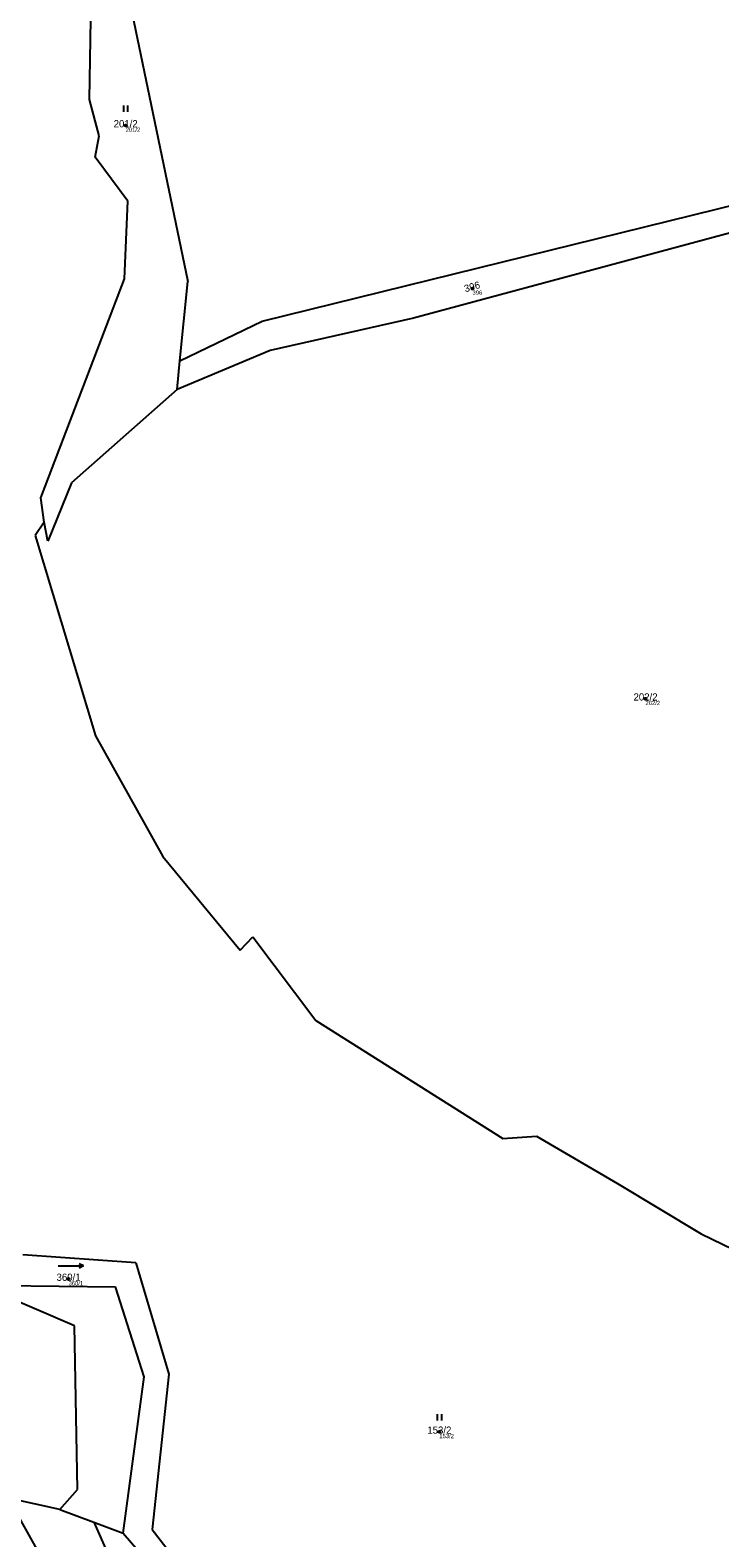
# Model space of a CAD drawing. Extents: x -868010 to -864567, y -1041968 to -1040406.
# Drawn here: x -866804.6 to -866641.3, y -1041599 to -1041242.1 of the extents above; entities that cross this region are included whole.
import ezdxf

# ---------------------------------------------------------------- set-up
doc = ezdxf.new("R2010")
doc.units = 0
for name, color, linetype in [('Definiční body', 7, 'Continuous'), ('Hranice parcel', 7, 'Continuous'), ('Parcelní čísla', 7, 'Continuous'), ('Značky kultur', 7, 'Continuous')]:
    doc.layers.add(name, color=color, linetype=linetype)

msp = doc.modelspace()

# ---------------------------------------------------------------- linework, layer by layer
at = {"layer": 'Definiční body'}
for centre in [(-866781.99, -1041264.71994), (-866699.87, -1041303.28994), (-866658.91, -1041400.40994), (-866795.51, -1041537.76994), (-866707.72, -1041573.95994)]:
    msp.add_circle(centre, 0.25, dxfattribs=at)
at = {"layer": 'Hranice parcel'}
for p, q in [((-866786.48, -1041209.4), (-866767.3, -1041301.64)), ((-866790.52, -1041258.58), (-866790.27, -1041239.55)), ((-866788.22, -1041267.14), (-866790.52, -1041258.58)), ((-866789.24, -1041272.25), (-866788.22, -1041267.14)), ((-866781.45, -1041282.6), (-866789.24, -1041272.25)), ((-866782.23, -1041301.03), (-866781.45, -1041282.6)), ((-866749.65, -1041311.02), (-866636.33, -1041283.07)), ((-866634.71, -1041289.05), (-866713.87, -1041310.31)), ((-866802.06, -1041352.84), (-866782.23, -1041301.03)), ((-866769.16, -1041320.39), (-866767.3, -1041301.64)), ((-866769.16, -1041320.39), (-866749.65, -1041311.02)), ((-866713.87, -1041310.31), (-866747.74, -1041318)), ((-866747.74, -1041318), (-866769.83, -1041327.19)), ((-866769.83, -1041327.19), (-866769.16, -1041320.39)), ((-866769.83, -1041327.19), (-866794.78, -1041349.34)), ((-866794.78, -1041349.34), (-866800.44, -1041363.1)), ((-866801.25, -1041358.65), (-866802.06, -1041352.84)), ((-866801.25, -1041358.65), (-866803.41, -1041361.75)), ((-866800.44, -1041363.1), (-866801.25, -1041358.65)), ((-866803.41, -1041361.75), (-866789.11, -1041409.23)), ((-866789.11, -1041409.23), (-866773.21, -1041437.76)), ((-866773.21, -1041437.76), (-866754.86, -1041459.89)), ((-866754.86, -1041459.89), (-866751.9, -1041456.78)), ((-866751.9, -1041456.78), (-866736.95, -1041476.54)), ((-866736.95, -1041476.54), (-866692.71, -1041504.47)), ((-866692.71, -1041504.47), (-866684.75, -1041503.93)), ((-866684.75, -1041503.93), (-866665.52, -1041515.19)), ((-866665.52, -1041515.19), (-866645.69, -1041527.09)), ((-866645.69, -1041527.09), (-866618.99, -1041540.04)), ((-866794.08, -1041548.87), (-866836.34, -1041530.65)), ((-866779.6, -1041533.91), (-866806.36, -1041532.08)), ((-866779.6, -1041533.91), (-866771.74, -1041560.26)), ((-866811.05, -1041539.28), (-866784.41, -1041539.63)), ((-866777.57, -1041560.94), (-866784.41, -1041539.63)), ((-866793.37, -1041587.63), (-866794.08, -1041548.87)), ((-866782.54, -1041597.89), (-866777.57, -1041560.94)), ((-866771.74, -1041560.26), (-866775.74, -1041597.09)), ((-866797.58, -1041592.36), (-866793.37, -1041587.63)), ((-866797.58, -1041592.36), (-866809.71, -1041589.61)), ((-866797.21, -1041612.03), (-866809.71, -1041589.61)), ((-866797.58, -1041592.36), (-866789.54, -1041595.32)), ((-866789.54, -1041595.32), (-866782.54, -1041597.89)), ((-866789.54, -1041595.32), (-866786.14, -1041602.99)), ((-866782.54, -1041597.89), (-866704.53, -1041688.75)), ((-866775.74, -1041597.09), (-866733.9, -1041650.81))]:
    msp.add_line(p, q, dxfattribs=at)
at = {"layer": 'Značky kultur'}
for p, q in [((-866782.441, -1041261.48), (-866782.441, -1041259.98)), ((-866781.44, -1041261.48), (-866781.44, -1041259.98)), ((-866791.993, -1041534.679), (-866792.97, -1041534.177)), ((-866797.993, -1041534.679), (-866791.993, -1041534.679)), ((-866791.993, -1041534.679), (-866792.97, -1041535.18)), ((-866708.131, -1041571.26), (-866708.131, -1041569.76)), ((-866707.13, -1041571.26), (-866707.13, -1041569.76))]:
    msp.add_line(p, q, dxfattribs=at)

# ---------------------------------------------------------------- texts
at = {"layer": 'Definiční body'}
for s, p in [('201/2', (-866781.99, -1041266.209)), ('396', (-866699.87, -1041304.779)), ('202/2', (-866658.91, -1041401.899)), ('360/1', (-866795.51, -1041539.259)), ('153/2', (-866707.72, -1041575.449))]:
    msp.add_text(s, height=0.999996, dxfattribs=at).set_placement(p)
at = {"layer": 'Parcelní čísla'}
for s, p in [('201/2', (-866784.826, -1041265.145)), ('202/2', (-866661.746, -1041400.835)), ('360/1', (-866798.346, -1041538.195)), ('153/2', (-866710.556, -1041574.385))]:
    msp.add_text(s, height=1.699998, dxfattribs=at).set_placement(p)
msp.add_text('396', height=1.699998, rotation=16, dxfattribs=at).set_placement((-866701.57, -1041304.219))

doc.saveas('drawing.dxf')
